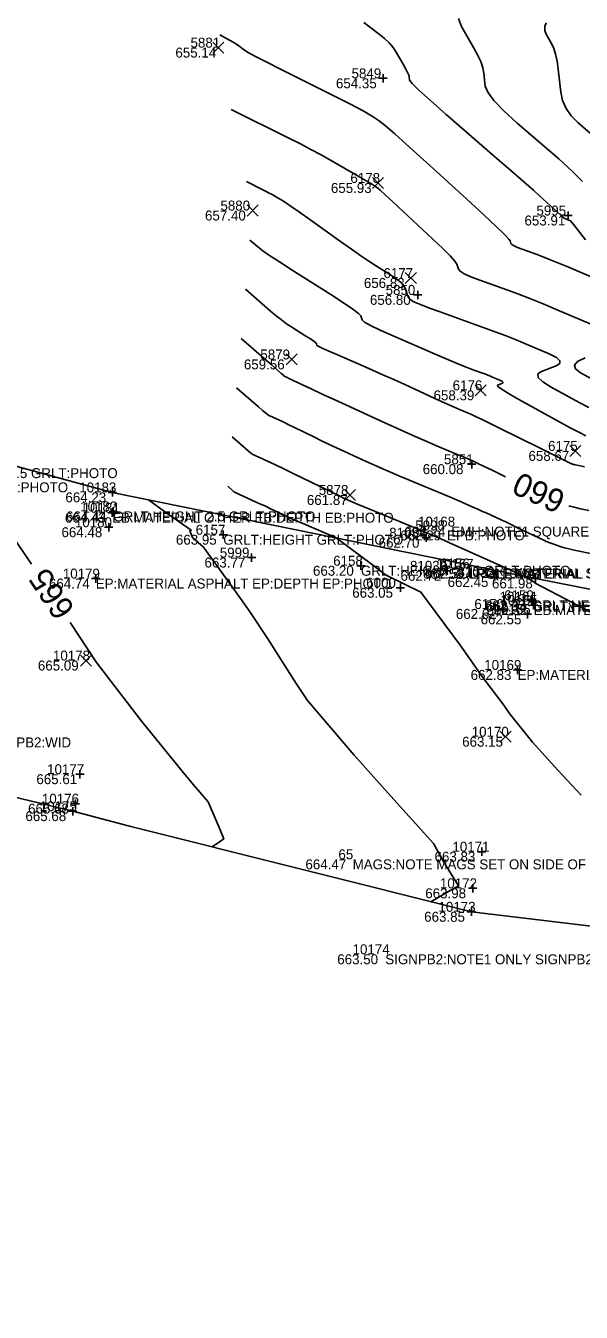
# Model space of a CAD drawing. Extents: x 2129350 to 2137777, y 657588 to 659885.
# Drawn here: x 2132748 to 2132814.9, y 658773.5 to 658928.5 of the extents above; entities that cross this region are included whole.
import ezdxf

# ---------------------------------------------------------------- set-up
doc = ezdxf.new("R2010")
doc.units = 0
for name, color, linetype in [('DT_X_Contour_Major', 7, 'Continuous'), ('DT_X_Contour_Minor', 7, 'Continuous'), ('DT_X_TIN_Hull', 7, 'Continuous'), ('SV_X_Random_Point', 7, 'Continuous'), ('SV_X_Shot_Marker', 7, 'Continuous'), ('SV_X_Text_Comment', 7, 'Continuous'), ('SV_X_Text_Elevation', 7, 'Continuous'), ('SV_X_Text_Name', 7, 'Continuous')]:
    doc.layers.add(name, color=color, linetype=linetype)

msp = doc.modelspace()

# ---------------------------------------------------------------- linework, layer by layer
at = {"layer": 'DT_X_Contour_Major'}
for points in [[(2132771.36, 658927.4), (2132772.98, 658926.51), (2132773.12, 658926.43), (2132773.2, 658926.38), (2132773.32, 658926.3), (2132773.49, 658926.17), (2132774.34, 658925.53), (2132774.79, 658925.26), (2132775.66, 658924.78), (2132776.96, 658924.12), (2132778.67, 658923.25), (2132783.82, 658920.69), (2132785.57, 658919.81), (2132786.95, 658919.11), (2132787.96, 658918.59), (2132788.61, 658918.23), (2132789.84, 658917.52), (2132790.44, 658917.11), (2132791.3, 658916.43), (2132792.43, 658915.46), (2132793.82, 658914.21), (2132797.9, 658910.51), (2132799.34, 658909.2), (2132800.59, 658908.06), (2132801.66, 658907.07), (2132802.54, 658906.25), (2132804.65, 658904.29), (2132805.35, 658903.63), (2132805.85, 658903.12), (2132806.17, 658902.77), (2132806.3, 658902.57), (2132806.4, 658902.26), (2132806.51, 658902.12), (2132806.78, 658901.96), (2132807.19, 658901.78), (2132807.75, 658901.56), (2132809.45, 658900.95), (2132810.17, 658900.69), (2132811.04, 658900.34), (2132812.07, 658899.92), (2132813.25, 658899.42), (2132816.62, 658897.98)], [(2132805.77, 658874.13), (2132805.36, 658874.33), (2132804.06, 658874.96), (2132803.11, 658875.42), (2132802.49, 658875.72), (2132802.22, 658875.86), (2132801.94, 658875.99), (2132801.74, 658876.09), (2132801.32, 658876.27), (2132800.7, 658876.53), (2132799.86, 658876.88), (2132797.36, 658877.93), (2132796.27, 658878.39), (2132794.89, 658879), (2132793.21, 658879.76), (2132791.24, 658880.66), (2132785.58, 658883.25), (2132783.69, 658884.11), (2132782.27, 658884.77), (2132781.31, 658885.21), (2132780.82, 658885.45), (2132780.12, 658885.79), (2132779.88, 658885.91), (2132779.7, 658886), (2132779.56, 658886.06), (2132779.48, 658886.1), (2132779.32, 658886.17), (2132779.27, 658886.19), (2132779.23, 658886.21), (2132779.2, 658886.22), (2132779.19, 658886.23), (2132779.16, 658886.24), (2132779.06, 658886.33), (2132778.76, 658886.59), (2132778.26, 658887.02), (2132777.58, 658887.62), (2132773.93, 658890.8)], [(2132748.72, 658863.6), (2132748.23, 658864.33), (2132746.5, 658866.86), (2132742.65, 658871.71), (2132742.17, 658872.93), (2132741.44, 658873.87), (2132735.65, 658877.07), (2132733.28, 658878.36), (2132730.2, 658879.96)], [(2132815.77, 658870.09), (2132814.79, 658870.3), (2132814.03, 658870.47), (2132813.51, 658870.6), (2132813.39, 658870.63)], [(2132770.45, 658829.55), (2132771.46, 658830.22), (2132771.85, 658830.52), (2132771.41, 658831.6), (2132769.96, 658834.97), (2132768.19, 658837.03), (2132766.84, 658838.69), (2132761.98, 658844.64), (2132756.52, 658851.77), (2132755.43, 658853.42), (2132753.37, 658856.6)]]:
    msp.add_lwpolyline(points, dxfattribs=at)
at = {"layer": 'DT_X_Contour_Minor'}
for points in [[(2132800.11, 658929.34), (2132800.47, 658928.4), (2132801.92, 658925.88), (2132802.4, 658924.98), (2132802.77, 658924.16), (2132803.01, 658923.43), (2132803.14, 658922.79), (2132803.32, 658921.2), (2132803.61, 658920.47), (2132804.35, 658919.49), (2132805.54, 658918.25), (2132807.18, 658916.76), (2132812.16, 658912.44), (2132813.81, 658910.94), (2132815.03, 658909.71)], [(2132788.69, 658928.89), (2132790.55, 658927.49), (2132791.21, 658926.96), (2132791.77, 658926.41), (2132792.23, 658925.86), (2132792.61, 658925.29), (2132793.48, 658923.77), (2132793.77, 658923.25), (2132793.98, 658922.84), (2132794.12, 658922.53), (2132794.18, 658922.32), (2132794.22, 658921.91), (2132794.51, 658921.53), (2132795.34, 658920.72), (2132796.71, 658919.48), (2132798.62, 658917.8), (2132804.43, 658912.75), (2132806.41, 658911.03), (2132807.96, 658909.67), (2132809.11, 658908.66), (2132809.84, 658908.01), (2132812.05, 658906), (2132812.41, 658905.67), (2132812.64, 658905.46), (2132812.68, 658905.42), (2132812.71, 658905.39), (2132812.72, 658905.37), (2132812.72, 658905.35), (2132812.73, 658905.34), (2132812.75, 658905.32), (2132812.79, 658905.31), (2132813.03, 658905.22), (2132813.19, 658905.15), (2132813.56, 658905), (2132813.83, 658904.71), (2132814.43, 658903.95), (2132815.37, 658902.71)], [(2132810.64, 658928.83), (2132810.47, 658928.38), (2132810.47, 658927.92), (2132810.65, 658927.47), (2132811.34, 658926.26), (2132811.59, 658925.73), (2132811.79, 658925.05), (2132811.97, 658924.23), (2132812.1, 658923.27), (2132812.41, 658920.49), (2132812.63, 658919.48), (2132813.05, 658918.53), (2132813.66, 658917.65), (2132814.48, 658916.82), (2132816.91, 658914.71)], [(2132772.76, 658918.41), (2132779.6, 658915), (2132781.02, 658914.28), (2132782.34, 658913.59), (2132783.56, 658912.93), (2132784.69, 658912.3), (2132787.56, 658910.64), (2132788.52, 658910.08), (2132789.25, 658909.65), (2132789.75, 658909.35), (2132790.01, 658909.18), (2132790.4, 658908.91), (2132790.69, 658908.66), (2132791.29, 658908.11), (2132792.2, 658907.28), (2132793.41, 658906.16), (2132797.03, 658902.77), (2132798.23, 658901.63), (2132799.1, 658900.75), (2132799.66, 658900.13), (2132799.89, 658899.77), (2132800.08, 658899.17), (2132800.29, 658898.91), (2132800.8, 658898.61), (2132801.59, 658898.25), (2132802.67, 658897.84), (2132805.93, 658896.67), (2132807.23, 658896.18), (2132808.69, 658895.61), (2132810.3, 658894.96), (2132812.07, 658894.21), (2132816.99, 658892.11)], [(2132774.59, 658909.7), (2132776.55, 658908.73), (2132776.95, 658908.53), (2132777.33, 658908.33), (2132777.68, 658908.14), (2132778, 658907.96), (2132778.82, 658907.48), (2132779.26, 658907.2), (2132779.98, 658906.72), (2132780.96, 658906.03), (2132782.21, 658905.14), (2132785.91, 658902.5), (2132787.22, 658901.57), (2132788.35, 658900.78), (2132789.32, 658900.12), (2132790.13, 658899.6), (2132792.04, 658898.39), (2132792.68, 658897.95), (2132793.17, 658897.56), (2132793.49, 658897.2), (2132793.67, 658896.88), (2132793.92, 658896.09), (2132794.04, 658895.82), (2132794.22, 658895.58), (2132794.45, 658895.39), (2132794.72, 658895.24), (2132795.54, 658894.89), (2132795.99, 658894.7), (2132796.74, 658894.42), (2132797.78, 658894.04), (2132799.11, 658893.56), (2132803.07, 658892.14), (2132804.5, 658891.62), (2132805.82, 658891.12), (2132807.05, 658890.63), (2132808.17, 658890.17), (2132811.03, 658888.94), (2132811.89, 658888.51), (2132812.31, 658888.13), (2132812.29, 658887.8), (2132811.84, 658887.52), (2132810.07, 658886.84), (2132809.64, 658886.53), (2132809.7, 658886.11), (2132810.23, 658885.59), (2132811.25, 658884.95), (2132814.61, 658883.11), (2132815.78, 658882.48)], [(2132775, 658902.66), (2132776.14, 658901.67), (2132776.57, 658901.35), (2132777.37, 658900.8), (2132778.55, 658900.03), (2132780.1, 658899.04), (2132784.74, 658896.1), (2132786.27, 658895.11), (2132787.38, 658894.35), (2132788.07, 658893.83), (2132788.34, 658893.53), (2132788.5, 658893.05), (2132788.78, 658892.79), (2132789.51, 658892.38), (2132790.68, 658891.81), (2132792.31, 658891.09), (2132797.23, 658888.96), (2132798.9, 658888.24), (2132800.21, 658887.69), (2132801.16, 658887.3), (2132801.75, 658887.07), (2132802.85, 658886.67), (2132803.25, 658886.53), (2132803.62, 658886.39), (2132803.96, 658886.25), (2132804.28, 658886.12), (2132805.07, 658885.78), (2132805.31, 658885.66), (2132805.43, 658885.55), (2132805.42, 658885.46), (2132805.3, 658885.38), (2132804.8, 658885.19), (2132804.85, 658885.02), (2132805.35, 658884.64), (2132806.3, 658884.05), (2132807.71, 658883.26), (2132812.08, 658880.86), (2132813.55, 658880.06), (2132814.67, 658879.46), (2132815.44, 658879.07)], [(2132774.47, 658896.73), (2132777.49, 658894.09), (2132778.14, 658893.55), (2132778.78, 658893.04), (2132779.41, 658892.58), (2132780.04, 658892.16), (2132781.72, 658891.1), (2132782.27, 658890.75), (2132782.67, 658890.47), (2132782.92, 658890.28), (2132783.01, 658890.18), (2132783.07, 658890), (2132783.23, 658889.88), (2132783.69, 658889.65), (2132784.43, 658889.31), (2132785.45, 658888.86), (2132788.57, 658887.51), (2132789.76, 658886.99), (2132791.01, 658886.44), (2132792.3, 658885.86), (2132793.64, 658885.25), (2132797.27, 658883.58), (2132798.51, 658883.02), (2132799.49, 658882.57), (2132800.23, 658882.24), (2132800.71, 658882.04), (2132801.66, 658881.64), (2132802.14, 658881.42), (2132802.87, 658881.08), (2132803.84, 658880.61), (2132805.05, 658880), (2132809.83, 658877.62), (2132810.8, 658877.13), (2132811.53, 658876.77), (2132812.01, 658876.54), (2132813.7, 658875.72), (2132813.75, 658875.71), (2132813.78, 658875.7), (2132813.82, 658875.68), (2132813.94, 658875.64), (2132814.01, 658875.62), (2132814.14, 658875.59), (2132814.33, 658875.55), (2132814.57, 658875.5), (2132815.28, 658875.35)], [(2132815.33, 658888.49), (2132814.44, 658888.04), (2132814.05, 658887.59), (2132814.17, 658887.13), (2132814.79, 658886.65), (2132817.13, 658885.37)], [(2132817.1, 658864.66), (2132814.83, 658865.14), (2132814.04, 658865.31), (2132813.39, 658865.46), (2132812.87, 658865.6), (2132812.47, 658865.72), (2132811.32, 658866.11), (2132811.1, 658866.19), (2132810.96, 658866.24), (2132810.89, 658866.26), (2132810.8, 658866.29), (2132810.67, 658866.35), (2132810.36, 658866.5), (2132809.85, 658866.74), (2132809.16, 658867.08), (2132807.05, 658868.09), (2132806.34, 658868.44), (2132805.79, 658868.7), (2132805.4, 658868.89), (2132805.17, 658868.99), (2132804.78, 658869.17), (2132804.65, 658869.23), (2132804.56, 658869.27), (2132804.46, 658869.31), (2132804.41, 658869.34), (2132804.36, 658869.36), (2132804.27, 658869.4), (2132804.12, 658869.46), (2132803.34, 658869.82), (2132803.08, 658869.93), (2132802.74, 658870.08), (2132802.33, 658870.27), (2132801.83, 658870.49), (2132800.42, 658871.13), (2132799.85, 658871.38), (2132799.23, 658871.65), (2132798.54, 658871.94), (2132797.79, 658872.25), (2132795.71, 658873.11), (2132794.3, 658873.69), (2132793.71, 658873.94), (2132793.19, 658874.15), (2132791.92, 658874.69), (2132791.37, 658874.92), (2132790.7, 658875.21), (2132789.91, 658875.57), (2132788.99, 658875.99), (2132786.36, 658877.19), (2132785.4, 658877.64), (2132784.46, 658878.08), (2132783.55, 658878.52), (2132782.67, 658878.94), (2132780.37, 658880.07), (2132779.59, 658880.45), (2132778.98, 658880.75), (2132778.54, 658880.96), (2132778.26, 658881.09), (2132777.75, 658881.32), (2132777.58, 658881.4), (2132777.45, 658881.45), (2132777.35, 658881.5), (2132777.3, 658881.52), (2132777.22, 658881.56), (2132777.12, 658881.63), (2132776.89, 658881.83), (2132776.52, 658882.14), (2132776.03, 658882.57), (2132773.39, 658884.87)], [(2132817.24, 658857.17), (2132809.31, 658861.32), (2132809.29, 658861.42), (2132808, 658862.16), (2132799.03, 658866.19), (2132797.91, 658866.69), (2132796.75, 658867.19), (2132795.57, 658867.7), (2132794.36, 658868.2), (2132790.01, 658869.99), (2132788.62, 658870.57), (2132788.32, 658870.7), (2132786.19, 658871.62), (2132786, 658871.72), (2132784.69, 658872.35), (2132780.22, 658874.55), (2132779.08, 658875.11), (2132778.17, 658875.55), (2132777.49, 658875.87), (2132777.05, 658876.08), (2132775.27, 658876.87), (2132775.18, 658876.93), (2132775.02, 658877.06), (2132774.78, 658877.26), (2132774.47, 658877.53), (2132772.85, 658878.94)], [(2132814.88, 658835.77), (2132812.07, 658838.8), (2132808.99, 658842.16), (2132806.25, 658845.62), (2132805.54, 658846.61), (2132802.89, 658850.1), (2132801.56, 658852.1), (2132800.29, 658853.84), (2132795.57, 658860.24), (2132791.47, 658862.24), (2132791.27, 658862.38), (2132789.73, 658863.52), (2132785.39, 658866.77), (2132781.48, 658868.46), (2132781.16, 658868.6), (2132780.81, 658868.75), (2132779.86, 658869.17), (2132779.5, 658869.32), (2132779.15, 658869.49), (2132778.79, 658869.65), (2132778.43, 658869.83), (2132777.47, 658870.3), (2132777.1, 658870.48), (2132776.7, 658870.67), (2132776.28, 658870.86), (2132775.83, 658871.06), (2132773.66, 658872.04), (2132773.33, 658872.19), (2132773.25, 658872.23), (2132773.15, 658872.3), (2132773.04, 658872.38), (2132772.92, 658872.48), (2132772.32, 658873.01)], [(2132796.78, 658822.95), (2132798.32, 658823.84), (2132800.11, 658824.86), (2132798.3, 658827.79), (2132797.09, 658829.96), (2132791.59, 658836.05), (2132787.55, 658840.6), (2132781.93, 658847.19), (2132780.57, 658849.25), (2132777.14, 658854.6), (2132775.03, 658857.85), (2132773.2, 658860.43), (2132769.42, 658865.68), (2132768.1, 658866.81), (2132767.78, 658867.65), (2132767.93, 658867.7), (2132764.87, 658869.83), (2132762.78, 658871.37)]]:
    msp.add_lwpolyline(points, dxfattribs=at)
at = {"layer": 'DT_X_TIN_Hull'}
for points in [[(2132782.91, 658867.27), (2132758.43, 658872.26), (2132736.24, 658878.31)], [(2133204.08, 658850.45), (2133155, 658844.59), (2133130.09, 658842.8), (2133105.15, 658841.01), (2133080.15, 658840.78), (2133055.15, 658840.54), (2133030.15, 658840.31), (2133005.16, 658840.07), (2132983.95, 658844.14), (2132984.08, 658845.64), (2132982.08, 658846.17), (2132955.89, 658842.88), (2132906.71, 658846.7), (2132856.29, 658852.67), (2132809.35, 658861.89), (2132807.38, 658862.29), (2132782.91, 658867.27)], [(2132743.37, 658836.36), (2132753.67, 658833.85), (2132760.52, 658832.04), (2132801.65, 658821.73), (2132824.47, 658819), (2132855.23, 658817.2), (2132859.5, 658790.97), (2132816.21, 658764.41)]]:
    msp.add_lwpolyline(points, dxfattribs=at)
at = {"layer": 'SV_X_Random_Point'}
for p, q in [((2132770.52, 658925.18), (2132771.85, 658926.52)), ((2132770.52, 658926.52), (2132771.85, 658925.18)), ((2132789.73, 658908.87), (2132791.06, 658910.21)), ((2132789.73, 658910.21), (2132791.06, 658908.87)), ((2132774.66, 658905.55), (2132775.99, 658906.89)), ((2132774.66, 658906.89), (2132775.99, 658905.55)), ((2132793.7, 658897.42), (2132795.04, 658898.75)), ((2132793.7, 658898.75), (2132795.04, 658897.42)), ((2132779.34, 658887.62), (2132780.68, 658888.95)), ((2132779.34, 658888.95), (2132780.68, 658887.62)), ((2132802.11, 658883.89), (2132803.44, 658885.23)), ((2132802.11, 658885.23), (2132803.44, 658883.89)), ((2132813.51, 658876.59), (2132814.84, 658877.92)), ((2132813.51, 658877.92), (2132814.84, 658876.59)), ((2132786.37, 658871.28), (2132787.71, 658872.62)), ((2132786.37, 658872.62), (2132787.71, 658871.28)), ((2132754.59, 658851.33), (2132755.93, 658852.67)), ((2132754.59, 658852.67), (2132755.93, 658851.33)), ((2132805.08, 658842.16), (2132806.42, 658843.49)), ((2132805.08, 658843.49), (2132806.42, 658842.16))]:
    msp.add_line(p, q, dxfattribs=at)
at = {"layer": 'SV_X_Shot_Marker'}
for p, q in [((2132790.52, 658922.15), (2132791.52, 658922.15)), ((2132791.02, 658922.65), (2132791.02, 658921.65)), ((2132791.02, 658922.15), (2132791.02, 658922.15)), ((2132813.29, 658906.12), (2132813.29, 658905.12)), ((2132812.79, 658905.62), (2132813.79, 658905.62)), ((2132813.29, 658905.62), (2132813.29, 658905.62)), ((2132795.2, 658896.56), (2132795.2, 658895.56)), ((2132794.7, 658896.06), (2132795.7, 658896.06)), ((2132795.2, 658896.06), (2132795.2, 658896.06)), ((2132801.19, 658875.66), (2132802.19, 658875.66)), ((2132801.69, 658876.16), (2132801.69, 658875.16)), ((2132801.69, 658875.66), (2132801.69, 658875.66)), ((2132757.94, 658872.26), (2132758.94, 658872.26)), ((2132758.44, 658872.76), (2132758.44, 658871.76)), ((2132758.44, 658872.26), (2132758.44, 658872.26)), ((2132758.42, 658870.31), (2132758.42, 658869.31)), ((2132758.54, 658870.47), (2132758.54, 658869.47)), ((2132757.92, 658869.81), (2132758.92, 658869.81)), ((2132758.04, 658869.97), (2132759.04, 658869.97)), ((2132758.42, 658869.81), (2132758.42, 658869.81)), ((2132758.54, 658869.97), (2132758.54, 658869.97)), ((2132757.51, 658868.06), (2132758.51, 658868.06)), ((2132758.01, 658868.56), (2132758.01, 658867.56)), ((2132758.01, 658868.06), (2132758.01, 658868.06)), ((2132771.29, 658867.16), (2132772.29, 658867.16)), ((2132771.79, 658867.66), (2132771.79, 658866.66)), ((2132771.79, 658867.16), (2132771.79, 658867.16)), ((2132796.22, 658867.3), (2132796.22, 658866.3)), ((2132795.72, 658866.8), (2132796.72, 658866.8)), ((2132796.22, 658866.8), (2132796.22, 658866.8)), ((2132774.69, 658864.41), (2132775.69, 658864.41)), ((2132775.19, 658864.91), (2132775.19, 658863.91)), ((2132775.19, 658864.41), (2132775.19, 658864.41)), ((2132787.85, 658863.42), (2132788.85, 658863.42)), ((2132788.35, 658863.92), (2132788.35, 658862.92)), ((2132788.35, 658863.42), (2132788.35, 658863.42)), ((2132798.23, 658862.81), (2132799.23, 658862.81)), ((2132798.73, 658863.31), (2132798.73, 658862.31)), ((2132798.73, 658862.81), (2132798.73, 658862.81)), ((2132804.44, 658862.56), (2132804.44, 658861.56)), ((2132755.95, 658861.88), (2132756.95, 658861.88)), ((2132756.45, 658862.38), (2132756.45, 658861.38)), ((2132756.45, 658861.88), (2132756.45, 658861.88)), ((2132793.1, 658861.27), (2132793.1, 658860.27)), ((2132803.94, 658862.06), (2132804.94, 658862.06)), ((2132804.44, 658862.06), (2132804.44, 658862.06)), ((2132808.85, 658861.89), (2132809.85, 658861.89)), ((2132809.35, 658862.39), (2132809.35, 658861.39)), ((2132809.35, 658861.89), (2132809.35, 658861.89)), ((2132792.6, 658860.77), (2132793.6, 658860.77)), ((2132793.1, 658860.77), (2132793.1, 658860.77)), ((2132808.92, 658859.77), (2132808.92, 658858.77)), ((2132809.03, 658859.59), (2132809.03, 658858.59)), ((2132804.93, 658858.21), (2132805.93, 658858.21)), ((2132805.43, 658858.71), (2132805.43, 658857.71)), ((2132805.43, 658858.21), (2132805.43, 658858.21)), ((2132808.4, 658858.07), (2132808.4, 658857.07)), ((2132808.42, 658859.27), (2132809.42, 658859.27)), ((2132808.53, 658859.09), (2132809.53, 658859.09)), ((2132808.63, 658858.69), (2132809.63, 658858.69)), ((2132808.92, 658859.27), (2132808.92, 658859.27)), ((2132809.03, 658859.09), (2132809.03, 658859.09)), ((2132809.13, 658859.19), (2132809.13, 658858.19)), ((2132809.13, 658858.69), (2132809.13, 658858.69)), ((2132807.9, 658857.57), (2132808.9, 658857.57)), ((2132808.4, 658857.57), (2132808.4, 658857.57)), ((2132806.71, 658850.87), (2132807.71, 658850.87)), ((2132807.21, 658851.37), (2132807.21, 658850.37)), ((2132807.21, 658850.87), (2132807.21, 658850.87)), ((2132754.04, 658838.31), (2132755.04, 658838.31)), ((2132754.54, 658838.81), (2132754.54, 658837.81)), ((2132754.54, 658838.31), (2132754.54, 658838.31)), ((2132753.49, 658834.75), (2132754.49, 658834.75)), ((2132753.99, 658835.25), (2132753.99, 658834.25)), ((2132753.99, 658834.75), (2132753.99, 658834.75)), ((2132753.17, 658833.85), (2132754.17, 658833.85)), ((2132753.67, 658834.35), (2132753.67, 658833.35)), ((2132753.67, 658833.85), (2132753.67, 658833.85)), ((2132802.4, 658828.97), (2132803.4, 658828.97)), ((2132802.9, 658829.47), (2132802.9, 658828.47)), ((2132802.9, 658828.97), (2132802.9, 658828.97)), ((2132801.31, 658824.56), (2132802.31, 658824.56)), ((2132801.81, 658825.06), (2132801.81, 658824.06)), ((2132801.81, 658824.56), (2132801.81, 658824.56)), ((2132801.65, 658822.23), (2132801.65, 658821.23)), ((2132801.15, 658821.73), (2132802.15, 658821.73)), ((2132801.65, 658821.73), (2132801.65, 658821.73))]:
    msp.add_line(p, q, dxfattribs=at)

# ---------------------------------------------------------------- texts
at = {"layer": 'DT_X_Contour_Major'}
for s, rotation, p in [('660', 155.29, (2132813.18, 658872.18)), ('665', 123.6058, (2132754.02, 658858.2))]:
    msp.add_text(s, height=2.8, rotation=rotation, dxfattribs=at).set_placement(p)
at = {"layer": 'SV_X_Text_Comment'}
for s, p in [('GRLT:HEIGHT 2.5 GRLT:PHOTO', (2132734.74, 658873.98)), ('EP:MATERIAL ASPHALT EP:DEPTH EP:PHOTO', (2132717.54, 658872.27)), ('EB:MATERIAL OTHER EB:DEPTH EB:PHOTO', (2132758.42, 658868.61)), ('GRLT:HEIGHT 2.5 GRLT:PHOTO', (2132758.54, 658868.77)), ('GRLT:HEIGHT GRLT:PHOTO', (2132771.79, 658865.96)), ('EPB:PHOTO', (2132798.72, 658866.48)), ('EMH:NOTE1 SQUARE EMH:NOTE2 EMH:PHOTO', (2132799.23, 658866.94)), ('GRLT:HEIGHT 2.25 GRLT:PHOTO', (2132788.35, 658862.22)), ('LPOLE:MATERIAL STEEL LPOLE:OWNER ODOT LPOLE:POLE# LPOLE:PHOTO', (2132801.28, 658861.9)), ('LPOLE:MATERIAL STEEL LPOLE:OWNER LPOLE:POLE# LPOLE:PHOTO', (2132801.45, 658861.85)), ('EP:MATERIAL ASPHALT EP:DEPTH EP:PHOTO', (2132756.45, 658860.68)), ('GRLT:HEIGHT 2.25 GRLT:PHOTO', (2132808.92, 658858.06)), ('GRLT:HEIGHT 2.5 GRLT:PHOTO', (2132809.03, 658857.89)), ('EB:MATERIAL OTHER EB:DEPTH EB:PHOTO', (2132809.13, 658857.49)), ('EP:MATERIAL ASPHALT EP:DEPTH EP:PHOTO', (2132807.21, 658849.67)), ('SIGNPB2:NOTE1 ADOPT A SIGNPB2:NOTE2 SIGNPB2:NOTE3 SIGNPB2:PHOTO SIGNPB2:WID', (2132682.32, 658841.54)), ('MAGS:NOTE MAGS SET ON SIDE OF EXIT RAMP/ WEST BOND MAGS:PHOTO', (2132787.36, 658826.85)), ('SIGNPB2:NOTE1 ONLY SIGNPB2:NOTE2 SIGNPB2:NOTE3 SIGNPB2:PHOTO SIGNPB2:WIDTH', (2132791.29, 658815.41))]:
    msp.add_text(s, height=1.2, dxfattribs=at).set_placement(p)
at = {"layer": 'SV_X_Text_Elevation'}
for s, p in [('655.14', (2132766.03, 658924.65)), ('654.35', (2132785.35, 658920.95)), ('655.93', (2132784.74, 658908.34)), ('657.40', (2132769.59, 658905.02)), ('653.91', (2132808.04, 658904.42)), ('656.83', (2132788.71, 658896.89)), ('656.80', (2132789.44, 658894.86)), ('659.56', (2132774.27, 658887.08)), ('658.39', (2132797.1, 658883.36)), ('658.67', (2132808.52, 658876.06)), ('660.08', (2132795.79, 658874.46)), ('664.23', (2132752.79, 658871.06)), ('661.87', (2132781.85, 658870.75)), ('664.43', (2132752.74, 658868.61)), ('664.44', (2132752.87, 658868.77)), ('664.48', (2132752.32, 658866.86)), ('663.95', (2132766.09, 658865.96)), ('662.29', (2132793.09, 658866.48)), ('662.24', (2132793.62, 658866.94)), ('662.70', (2132790.49, 658865.6)), ('663.77', (2132769.53, 658863.21)), ('663.20', (2132782.59, 658862.22)), ('662.72', (2132793.12, 658861.61)), ('662.53', (2132795.81, 658861.85)), ('662.51', (2132796.07, 658861.9)), ('664.74', (2132750.81, 658860.68)), ('662.45', (2132798.79, 658860.86)), ('661.98', (2132804.13, 658860.69)), ('663.05', (2132787.31, 658859.57)), ('662.62', (2132799.78, 658857.02)), ('662.33', (2132803.26, 658858.06)), ('662.34', (2132803.38, 658857.89)), ('662.32', (2132803.48, 658857.49)), ('662.55', (2132802.76, 658856.37)), ('665.09', (2132749.48, 658850.8)), ('662.83', (2132801.56, 658849.67)), ('663.15', (2132800.54, 658841.62)), ('665.61', (2132749.3, 658837.11)), ('665.68', (2132748.3, 658833.55)), ('665.68', (2132747.98, 658832.66)), ('663.83', (2132797.22, 658827.77)), ('664.47', (2132781.68, 658826.85)), ('664.47', (2132781.68, 658826.85)), ('663.98', (2132796.1, 658823.36)), ('663.85', (2132795.97, 658820.53)), ('663.50', (2132785.51, 658815.41))]:
    msp.add_text(s, height=1.2, dxfattribs=at).set_placement(p)
at = {"layer": 'SV_X_Text_Name'}
for s, p in [('5881', (2132767.85, 658925.85)), ('5849', (2132787.23, 658922.15)), ('6178', (2132787.09, 658909.54)), ('5880', (2132771.45, 658906.22)), ('5995', (2132809.48, 658905.62)), ('6177', (2132791.07, 658898.08)), ('5850', (2132791.33, 658896.06)), ('5879', (2132776.25, 658888.28)), ('6176', (2132799.4, 658884.56)), ('6175', (2132810.88, 658877.26)), ('5851', (2132798.35, 658875.66)), ('10183', (2132754.46, 658872.26)), ('5878', (2132783.28, 658871.95)), ('10182', (2132754.57, 658869.97)), ('10181', (2132754.87, 658869.81)), ('10180', (2132753.93, 658868.06)), ('5998', (2132794.9, 658867.68)), ('10168', (2132795.23, 658868.14)), ('6157', (2132768.47, 658867.16)), ('81034', (2132791.76, 658866.8)), ('5999', (2132771.37, 658864.41)), ('6158', (2132785.02, 658863.42)), ('81033', (2132794.26, 658862.81)), ('10167', (2132797.46, 658863.05)), ('6156', (2132797.89, 658863.1)), ('10179', (2132752.48, 658861.88)), ('81032', (2132799.98, 658862.06)), ('10163', (2132805.35, 658861.89)), ('6000', (2132788.99, 658860.77)), ('6150', (2132802.01, 658858.21)), ('10164', (2132805.04, 658859.09)), ('10165', (2132805.14, 658858.69)), ('6159', (2132805.59, 658859.27)), ('10166', (2132804.33, 658857.57)), ('10178', (2132751.29, 658852)), ('10169', (2132803.2, 658850.87)), ('10170', (2132801.69, 658842.82)), ('10177', (2132750.59, 658838.31)), ('10175', (2132749.71, 658833.85)), ('10176', (2132749.96, 658834.75)), ('10171', (2132799.37, 658828.97)), ('65', (2132785.65, 658828.05)), ('65', (2132785.65, 658828.05)), ('10172', (2132797.86, 658824.56)), ('10173', (2132797.69, 658821.73)), ('10174', (2132787.35, 658816.61))]:
    msp.add_text(s, height=1.2, dxfattribs=at).set_placement(p)

doc.saveas('drawing.dxf')
